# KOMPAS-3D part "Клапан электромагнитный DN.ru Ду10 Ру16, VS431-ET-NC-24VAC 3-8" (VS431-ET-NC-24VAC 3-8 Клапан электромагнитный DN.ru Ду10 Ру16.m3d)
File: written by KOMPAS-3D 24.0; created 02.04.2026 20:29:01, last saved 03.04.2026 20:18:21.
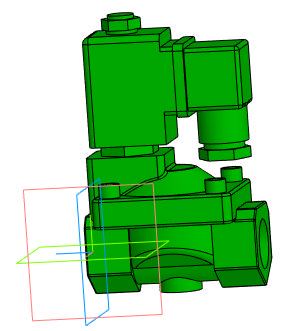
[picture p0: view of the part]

Document properties: Автор: artio; Полное имя файла: C:\Users\artio\OneDrive\Рабочий стол\Клапан электромагнитный DN.ru\VS431\VS431-ET-NC\VS431-ET-NC-24VAC\Ду10\VS431-ET-NC-24VAC 3-8 Клапан электромагнитный DN.ru Ду10 Ру16.m3d

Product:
- Body: Тело 1  | qty 1
    Масса: 1.030062
- Part/product: Клапан электромагнитный DN.ru Ду10 Ру16  | designation VS431-ET-NC-24VAC 3-8
    Масса: 0.62
    Раздел спецификации: Прочие изделия
    Примечание: D130-05634
    additional columns: ef56311e-7521-43dc-8291-0e6108b3d81d; VS400-ET-NC-220VAC 3-8; artio; c; Шероховатость не задана; Да

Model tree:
1. Операция без истории:1

Expressions: VS431-ET-NC-24VAC 3-8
